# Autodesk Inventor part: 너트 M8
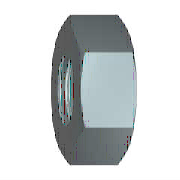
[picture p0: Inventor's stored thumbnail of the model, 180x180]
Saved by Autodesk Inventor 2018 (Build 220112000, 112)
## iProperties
IsCustomPart: 1
Created: 2012-02
Part Number: 너트 M8
Material: 강철, 연강
Description: 6각 너트
Document SubType Name: Modeling
Standard: KS B 1012
Designer: mduedu
Standards Organization: KS
Language: ko-KR
Size Designation: M8
Categories: <MemberInstance><Categories><Category DisplayName="조임쇠" InternalName="e4da775c-781d-43d5-af7c-5136215cf5a6" Mnemonic="FSTN"><Category DisplayName="너트" InternalN
Density: 1 g/cm^3
Appearance: 강철
Author: mduedu
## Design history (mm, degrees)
sketch "스케치1"
  geometry: L1 (-7.506, 0)-(-3.753, 6.5); L2 (-3.753, 6.5)-(3.753, 6.5); L3 (3.753, 6.5)-(7.506, 0); L4 (7.506, 0)-(3.753, -6.5); L5 (3.753, -6.5)-(-3.753, -6.5); L6 (-3.753, -6.5)-(-7.506, 0); 2 further points
  constraints: 12 end point, 1 coincident, 1 horizontal, 11 other
  dimensions: "d0" = 15.01111 distance of L3.end L1.start (= 1.1547 x SW)
extrude "본체" new body sketch "스케치1" distance "d1" = 5 (= KOH); taper "d2" = 0 deg
sketch "스케치2"
  geometry: L1 (0, 3.753)-(0, 7.506) reference; L2 (0, 7.506)-(5, 7.506) reference; L3 (5, 3.753)-(5, 7.506) reference; L4 (-1, 0)-(6, 0) reference; L5 (0.581, 7.506)-(0, 6.5); L6 (4.419, 7.506)-(5, 6.5)
  constraints: 4 end point, 4 point on line
  dimensions: "d3" = 30 deg angle of L1 L5 (= ANG1); "d4" = 30 deg angle of L3 L6 (= ANG2); "d5" = 13 diameter of L5.end L4 (= SW0); "d6" = 13 diameter of L6.end L4 (= SW01)
revolve "모따기1" sketch "스케치2" stored, may be unused: angle "d7" = 90 deg
sketch "스케치3"
  geometry: A1 r 6.5 centre (0, 0) between (-3.25, -5.629) and (3.25, -5.629) reference; 1 further point
  constraints: 1 coincident
hole "스레드" sketch "스케치3" at (0, 0) diameter "d25" = 6.647; stored, may be unused: countersink angle "d29" = 82 deg, drill point angle "d31" = 118 deg; dims "d26" = 6, "d27" = 4, "d28" = 2, "d30" = 8
workaxis "Work Axis1"
workplane "Work Plane1"
body "Solid1"
chamfer "모따기2" distance "d8" = 0.67658 (= -0.5 x GD1 + 0.5 x NND); stored, may be unused: angle "d9" = 30 deg, second distance "d40" = 0.67658 (= -0.5 x GD1 + 0.5 x NND)
chamfer "모따기3" distance "d10" = 0.67658 (= -0.5 x GD1 + 0.5 x NND); stored, may be unused: angle "d11" = 30 deg, second distance "d41" = 0.67658 (= -0.5 x GD1 + 0.5 x NND)
other parameters: "ANG1" = 30 deg [user parameter; used in 1 equation term], "ANG2" = 30 deg [user parameter; used in 1 equation term], "NND" = 8 [user parameter; used in 4 equation terms], "KOH" = 5 [user parameter; used in 1 equation term], "SW" = 13 [user parameter; used in 4 equation terms], "SW0" = 13 (= SW) [user parameter; used in 1 equation term], "SW01" = 13 (= SW) [user parameter; used in 1 equation term], "GD1" = 6.64684 (computed from THREADDIA, PTC, TOA) [user parameter; used in 4 equation terms], "d13" = 0, "d14" = 0, "d39" = 0, "d42" = 0, "GUL" = 0.67658 (= 0.541266 x PTC) [user parameter], "TPU" = 8 (computed from PTC) [user parameter], "THREADDIA" = 8 [user parameter; used in 1 equation term], "TOA" = 30 deg [user parameter; used in 1 equation term], "PTC" = 1.25 [user parameter; used in 4 equation terms], "E0" = 15.015 (= 1.155 x SW) [user parameter], "GAL" = 0.67658 (= 0.541266 x PTC) [user parameter]
